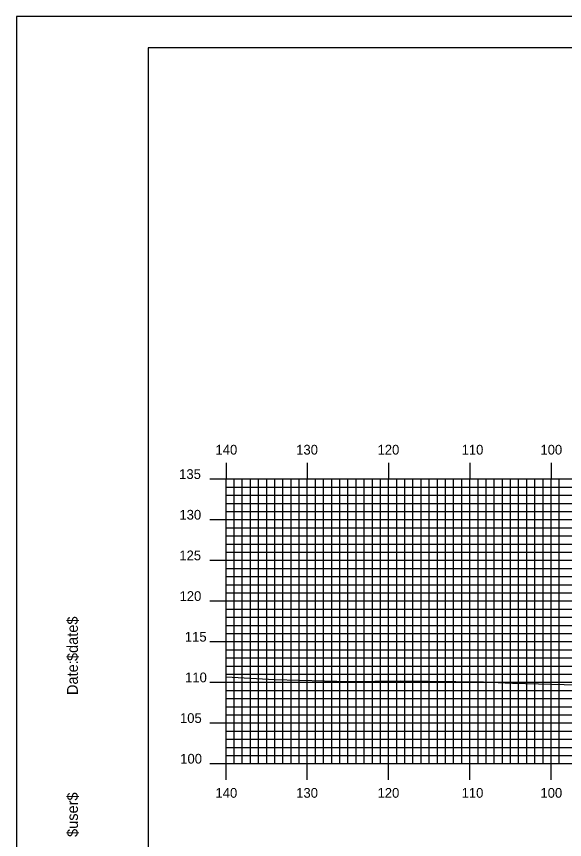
# Model space of a CAD drawing. Extents: x 1781467 to 1781810, y 442591 to 442811.
# Drawn here: x 1781466.6 to 1781534.1, y 442709.3 to 442810.5 of the extents above; entities that cross this region are included whole.
import ezdxf

# ---------------------------------------------------------------- set-up
doc = ezdxf.new("R2010")
doc.units = 0
for name, color, linetype in [('BORDER', 7, 'Continuous'), ('H_V ANNOTATION', 7, 'Continuous'), ('MAJOR', 7, 'Continuous'), ('MINOR', 7, 'Continuous'), ('PLOT BOUNDARY', 7, 'Continuous'), ('S_Roadway_Centerline', 7, 'Continuous')]:
    doc.layers.add(name, color=color, linetype=linetype)

msp = doc.modelspace()

# ---------------------------------------------------------------- linework, layer by layer
at = {"layer": 'BORDER'}
msp.add_lwpolyline([(1781482.81, 442596.67), (1781802.81, 442596.67), (1781802.81, 442806.67), (1781482.81, 442806.67)], close=True, dxfattribs=at)
at = {"layer": 'MAJOR'}
for p, q in [((1781492.41, 442755.67), (1781492.41, 442753.67)), ((1781502.41, 442755.67), (1781502.41, 442753.67)), ((1781512.41, 442755.67), (1781512.41, 442753.67)), ((1781522.41, 442755.67), (1781522.41, 442753.67)), ((1781532.41, 442755.67), (1781532.41, 442753.67)), ((1781490.4, 442753.67), (1781492.41, 442753.67)), ((1781492.41, 442753.67), (1781772.41, 442753.67)), ((1781492.41, 442718.67), (1781492.41, 442753.67)), ((1781492.41, 442718.67), (1781492.41, 442753.67)), ((1781492.41, 442753.67), (1781772.41, 442753.67)), ((1781502.41, 442718.67), (1781502.41, 442753.67)), ((1781512.41, 442718.67), (1781512.41, 442753.67)), ((1781522.41, 442718.67), (1781522.41, 442753.67)), ((1781532.41, 442718.67), (1781532.41, 442753.67)), ((1781490.4, 442748.67), (1781492.41, 442748.67)), ((1781492.41, 442748.67), (1781772.41, 442748.67)), ((1781490.4, 442743.67), (1781492.41, 442743.67)), ((1781492.41, 442743.67), (1781772.41, 442743.67)), ((1781490.4, 442738.67), (1781492.41, 442738.67)), ((1781492.41, 442738.67), (1781772.41, 442738.67)), ((1781490.4, 442733.67), (1781492.41, 442733.67)), ((1781492.41, 442733.67), (1781772.41, 442733.67)), ((1781490.4, 442728.67), (1781492.41, 442728.67)), ((1781492.41, 442728.67), (1781772.41, 442728.67)), ((1781490.4, 442723.67), (1781492.41, 442723.67)), ((1781492.41, 442723.67), (1781772.41, 442723.67)), ((1781490.4, 442718.67), (1781492.41, 442718.67)), ((1781492.41, 442718.67), (1781772.41, 442718.67)), ((1781492.41, 442718.67), (1781772.41, 442718.67)), ((1781492.41, 442716.66), (1781492.41, 442718.67)), ((1781502.41, 442716.66), (1781502.41, 442718.67)), ((1781512.41, 442716.66), (1781512.41, 442718.67)), ((1781522.41, 442716.66), (1781522.41, 442718.67)), ((1781532.41, 442716.66), (1781532.41, 442718.67))]:
    msp.add_line(p, q, dxfattribs=at)
at = {"layer": 'MINOR'}
for p, q in [((1781493.41, 442718.67), (1781493.41, 442753.67)), ((1781494.41, 442718.67), (1781494.41, 442753.67)), ((1781495.41, 442718.67), (1781495.41, 442753.67)), ((1781496.41, 442718.67), (1781496.41, 442753.67)), ((1781497.41, 442718.67), (1781497.41, 442753.67)), ((1781498.41, 442718.67), (1781498.41, 442753.67)), ((1781499.41, 442718.67), (1781499.41, 442753.67)), ((1781500.41, 442718.67), (1781500.41, 442753.67)), ((1781501.41, 442718.67), (1781501.41, 442753.67)), ((1781503.41, 442718.67), (1781503.41, 442753.67)), ((1781504.41, 442718.67), (1781504.41, 442753.67)), ((1781505.41, 442718.67), (1781505.41, 442753.67)), ((1781506.41, 442718.67), (1781506.41, 442753.67)), ((1781507.41, 442718.67), (1781507.41, 442753.67)), ((1781508.41, 442718.67), (1781508.41, 442753.67)), ((1781509.41, 442718.67), (1781509.41, 442753.67)), ((1781510.41, 442718.67), (1781510.41, 442753.67)), ((1781511.41, 442718.67), (1781511.41, 442753.67)), ((1781513.41, 442718.67), (1781513.41, 442753.67)), ((1781514.41, 442718.67), (1781514.41, 442753.67)), ((1781515.41, 442718.67), (1781515.41, 442753.67)), ((1781516.41, 442718.67), (1781516.41, 442753.67)), ((1781517.41, 442718.67), (1781517.41, 442753.67)), ((1781518.41, 442718.67), (1781518.41, 442753.67)), ((1781519.41, 442718.67), (1781519.41, 442753.67)), ((1781520.41, 442718.67), (1781520.41, 442753.67)), ((1781521.41, 442718.67), (1781521.41, 442753.67)), ((1781523.41, 442718.67), (1781523.41, 442753.67)), ((1781524.41, 442718.67), (1781524.41, 442753.67)), ((1781525.41, 442718.67), (1781525.41, 442753.67)), ((1781526.41, 442718.67), (1781526.41, 442753.67)), ((1781527.41, 442718.67), (1781527.41, 442753.67)), ((1781528.41, 442718.67), (1781528.41, 442753.67)), ((1781529.41, 442718.67), (1781529.41, 442753.67)), ((1781530.41, 442718.67), (1781530.41, 442753.67)), ((1781531.41, 442718.67), (1781531.41, 442753.67)), ((1781533.41, 442718.67), (1781533.41, 442753.67)), ((1781492.41, 442752.67), (1781772.41, 442752.67)), ((1781492.41, 442752.67), (1781494.41, 442752.67)), ((1781492.41, 442751.67), (1781772.41, 442751.67)), ((1781492.41, 442751.67), (1781494.41, 442751.67)), ((1781492.41, 442750.67), (1781772.41, 442750.67)), ((1781492.41, 442750.67), (1781494.41, 442750.67)), ((1781492.41, 442749.67), (1781772.41, 442749.67)), ((1781492.41, 442749.67), (1781494.41, 442749.67)), ((1781492.41, 442747.67), (1781772.41, 442747.67)), ((1781492.41, 442747.67), (1781494.41, 442747.67)), ((1781492.41, 442746.67), (1781772.41, 442746.67)), ((1781492.41, 442746.67), (1781494.41, 442746.67)), ((1781492.41, 442745.67), (1781772.41, 442745.67)), ((1781492.41, 442745.67), (1781494.41, 442745.67)), ((1781492.41, 442744.67), (1781772.41, 442744.67)), ((1781492.41, 442744.67), (1781494.41, 442744.67)), ((1781492.41, 442742.67), (1781772.41, 442742.67)), ((1781492.41, 442742.67), (1781494.41, 442742.67)), ((1781492.41, 442741.67), (1781772.41, 442741.67)), ((1781492.41, 442741.67), (1781494.41, 442741.67)), ((1781492.41, 442740.67), (1781772.41, 442740.67)), ((1781492.41, 442740.67), (1781494.41, 442740.67)), ((1781492.41, 442739.67), (1781772.41, 442739.67)), ((1781492.41, 442739.67), (1781494.41, 442739.67)), ((1781492.41, 442737.67), (1781772.41, 442737.67)), ((1781492.41, 442737.67), (1781494.41, 442737.67)), ((1781492.41, 442736.67), (1781772.41, 442736.67)), ((1781492.41, 442736.67), (1781494.41, 442736.67)), ((1781492.41, 442735.67), (1781772.41, 442735.67)), ((1781492.41, 442735.67), (1781494.41, 442735.67)), ((1781492.41, 442734.67), (1781772.41, 442734.67)), ((1781492.41, 442734.67), (1781494.41, 442734.67)), ((1781492.41, 442732.67), (1781772.41, 442732.67)), ((1781492.41, 442732.67), (1781494.41, 442732.67)), ((1781492.41, 442731.67), (1781772.41, 442731.67)), ((1781492.41, 442731.67), (1781494.41, 442731.67)), ((1781492.41, 442730.67), (1781772.41, 442730.67)), ((1781492.41, 442730.67), (1781494.41, 442730.67)), ((1781492.41, 442729.67), (1781772.41, 442729.67)), ((1781492.41, 442729.67), (1781494.41, 442729.67)), ((1781492.41, 442727.67), (1781772.41, 442727.67)), ((1781492.41, 442727.67), (1781494.41, 442727.67)), ((1781492.41, 442726.67), (1781772.41, 442726.67)), ((1781492.41, 442726.67), (1781494.41, 442726.67)), ((1781492.41, 442725.67), (1781772.41, 442725.67)), ((1781492.41, 442725.67), (1781494.41, 442725.67)), ((1781492.41, 442724.67), (1781772.41, 442724.67)), ((1781492.41, 442724.67), (1781494.41, 442724.67)), ((1781492.41, 442722.67), (1781772.41, 442722.67)), ((1781492.41, 442722.67), (1781494.41, 442722.67)), ((1781492.41, 442721.67), (1781772.41, 442721.67)), ((1781492.41, 442721.67), (1781494.41, 442721.67)), ((1781492.41, 442720.67), (1781772.41, 442720.67)), ((1781492.41, 442720.67), (1781494.41, 442720.67)), ((1781492.41, 442719.67), (1781772.41, 442719.67)), ((1781492.41, 442719.67), (1781494.41, 442719.67))]:
    msp.add_line(p, q, dxfattribs=at)
at = {"layer": 'PLOT BOUNDARY'}
msp.add_lwpolyline([(1781466.62, 442590.55), (1781806.62, 442590.55), (1781806.62, 442810.55), (1781466.62, 442810.55)], close=True, dxfattribs=at)
at = {"layer": 'S_Roadway_Centerline'}
msp.add_lwpolyline([(1781492.41, 442729.34), (1781498.39, 442729.01), (1781507.59, 442728.75), (1781513.83, 442728.85), (1781524.1, 442728.72), (1781527.64, 442728.58), (1781537.22, 442728.32), (1781545.64, 442728.37), (1781559.35, 442728.11), (1781569.07, 442727.79), (1781574.56, 442727.88), (1781583.78, 442728.01), (1781593.87, 442727.96), (1781606.48, 442727.73)], dxfattribs=at)

# ---------------------------------------------------------------- texts
at = {"layer": 'BORDER'}
for s, p in [('$date$', (1781474.18, 442731.28)), ('Date:', (1781474.18, 442727.1)), ('$user$', (1781474.18, 442709.65))]:
    msp.add_text(s, height=1.339, rotation=90, dxfattribs=at).set_placement(p)
at = {"layer": 'H_V ANNOTATION'}
for s, p in [('140', (1781491.11, 442756.67)), ('130', (1781501.04, 442756.67)), ('120', (1781511.05, 442756.67)), ('110', (1781521.39, 442756.67)), ('100', (1781531.09, 442756.67)), ('135', (1781486.64, 442753.67)), ('130', (1781486.67, 442748.67)), ('125', (1781486.66, 442743.67)), ('120', (1781486.69, 442738.67)), ('115', (1781487.34, 442733.67)), ('110', (1781487.37, 442728.67)), ('105', (1781486.74, 442723.67)), ('100', (1781486.77, 442718.67)), ('140', (1781491.11, 442714.47)), ('130', (1781501.04, 442714.47)), ('120', (1781511.05, 442714.47)), ('110', (1781521.39, 442714.47)), ('100', (1781531.09, 442714.47))]:
    msp.add_text(s, height=1.2, dxfattribs=at).set_placement(p)
at = {"layer": 'MAJOR'}
msp.add_text('-', height=0.012, dxfattribs=at).set_placement((1781492.4, 442718.67))

doc.saveas('drawing.dxf')
